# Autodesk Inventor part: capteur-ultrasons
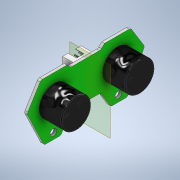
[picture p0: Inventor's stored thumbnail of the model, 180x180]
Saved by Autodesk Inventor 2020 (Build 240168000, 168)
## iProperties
Created: 2022-02
Part Number: capteur-ultrasons
Material: Générique
Document SubType Name: Modeling
Designer: bruno
Density: 1 g/cm^3
Appearance: Par défaut
Author: bruno
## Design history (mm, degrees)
sketch "Esquisse1"
  geometry: L1 (0, 0)-(20, 0); L2 (20, 0)-(20, 7.394); L3 (20, 8)-(0, 8); L4 (0, 7.149)-(0, 0); L5 (20.421, 8.436)-(22, 10.073); L6 (22, 10.073)-(22, 23.237); L7 (21.289, 24.513)-(10.698, 31.068); L8 (9.26, 31.144)-(-8.149, 22.782); L9 (-9, 21.43)-(-9, 14.225); L10 (-8.269, 12.937)-(-0.731, 8.436); C1 r 1.75 at (-5.582, 17.437); A1 r 1.5 centre (9.909, 29.792) between (10.698, 31.068) and (9.26, 31.144); A2 r 1.5 centre (-7.5, 21.43) between (-8.149, 22.782) and (-9, 21.43); A3 r 1.5 centre (-7.5, 14.225) between (-9, 14.225) and (-8.269, 12.937); A4 r 1.5 centre (-1.5, 7.149) between (0, 7.149) and (-0.731, 8.436); A5 r 1.5 centre (20.5, 23.237) between (22, 23.237) and (21.289, 24.513); A6 r 1.5 centre (21.5, 7.394) between (20.421, 8.436) and (20, 7.394); 4 further points
  constraints: 20 end point, 12 point on circle, 12 point on line, 12 tangent, 7 centre point, 5 equal radius, 2 parallel, 2 vertical, 1 horizontal, 1 perpendicular
  dimensions: "d0" = 20 distance of L3.end L3.start; "d1" = 8 distance of L3.start L1.end; "d2" = 2 distance between parallel lines of L6 L2; "d3" = 31.5 distance from line of L1 point (10, 31.5); "d4" = 12 distance from line of L6 point (10, 31.5); "d5" = 31 distance between parallel lines of L9 L6; "d6" = 9 distance of point (-9, 22.374) point (-9, 13.374); "d7" = 14 distance of L5.end point (22, 24.073); "d8" = 1.5 radius of A1; "d9" = 3.5 diameter of C1
extrude "Extrusion1" new body sketch "Esquisse1" distance "d10" = 1.5; taper "d11" = 0 deg
mirror "Symétrie1"
sketch "Esquisse2"
  geometry: L1 (-5, 19.693)-(5, 19.693); L2 (5, 19.693)-(5, 14.693); L3 (5, 14.693)-(-5, 14.693); L4 (-5, 14.693)-(-5, 19.693); L5 (0, 19.693)-(0, 20); L6 (7.394, 20)-(-7.394, 20) reference; L7 (-4.789, 19.493)-(4.822, 19.493); L8 (4.822, 19.493)-(4.822, 15.018); L9 (4.822, 15.018)-(-4.789, 15.018); L10 (-4.789, 15.018)-(-4.789, 19.493); 1 further point
  constraints: 18 end point, 4 parallel, 2 horizontal, 2 midpoint, 2 perpendicular, 1 vertical
  dimensions: "d12" = 10 distance of L2.end L3.end; "d13" = 5 distance of L1.end L2.end; "d14" = 0.2 distance between parallel lines of L7 L1
extrude "Extrusion2" join sketch "Esquisse2" distance "d15" = 6; taper "d16" = 0 deg
sketch "Esquisse3"
  geometry: L1 (-1.482, 7)-(-6.869, 7); L2 (-6.869, 7)-(-6.869, 3); L3 (-6.869, 3)-(-1.482, 3); L4 (-1.482, 3)-(-1.482, 7); L5 (0, 0)-(-6, 0) reference; L6 (0, 10)-(-6, 10) reference; 1 further point
  constraints: 8 end point, 2 parallel, 1 horizontal, 1 perpendicular
  dimensions: "d19" = 3 distance between parallel lines of L5 L3; "d20" = 3 distance between parallel lines of L6 L1
extrude "Extrusion3" cut sketch "Esquisse3" distance "d17" = 1; taper "d18" = 0 deg
sketch "Esquisse4" dims "d26" = 10
  geometry: L1 (-4.789, 19.493)-(-4.789, 15.018) reference; L2 (-4.789, 17.256)-(4.822, 17.256); L3 (4.822, 15.018)-(4.822, 19.493) reference; C1 r 0.37 at (-3.779, 17.256); C2 r 0.37 at (-1.379, 17.256); C3 r 0.37 at (1.021, 17.256); C4 r 0.37 at (3.421, 17.256); 1 further point
  constraints: 4 centre point, 2 end point, 2 midpoint, 1 horizontal, 1 point on line, 6 other
  dimensions: "d23" = 2.4 distance of C1.centre C2.centre
extrude "Extrusion4" join sketch "Esquisse4" distance "d28" = 6; taper "d29" = 0 deg
fillet "Congé1" dims "d30" = 0.2
sketch "Esquisse6"
  geometry: L1 (-10.073, 22)-(-23.237, 22) reference; C1 r 8 at (-17, 9); 1 further point
  constraints: 1 centre point
  dimensions: "d31" = 16 diameter of C1; "d32" = 13 distance from line of L1 C1.centre; "d33" = 17 horizontal distance of C1.centre point (0, 0)
extrude "Extrusion5" join sketch "Esquisse6" distance "d34" = 12; taper "d35" = 0 deg
fillet "Congé2" dims "d36" = 0.5
mirror "Symétrie2"
node "Solide1"
node "Plan de construction1"
